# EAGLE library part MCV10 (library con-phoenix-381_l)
Mini-Combicon 3.81mm vertikal 10polig (ohne Gegenstecker)
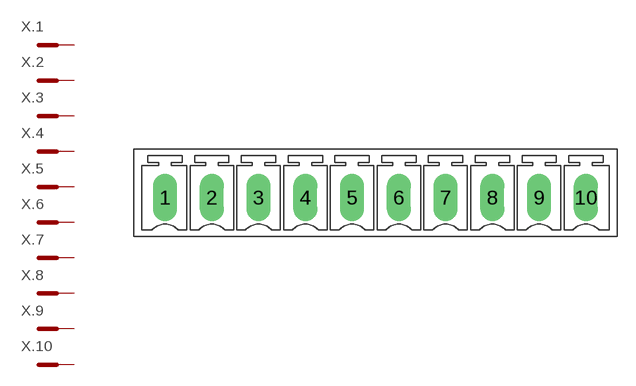
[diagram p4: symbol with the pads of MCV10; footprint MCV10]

Designator prefix X; gates .1=MCST .2=MCST .3=MCST .4=MCST .5=MCST .6=MCST .7=MCST .8=MCST .9=MCST .10=MCST

## MCV10  [MCV10]
1  .1:SK  pas
2  .2:SK  pas
3  .3:SK  pas
4  .4:SK  pas
5  .5:SK  pas
6  .6:SK  pas
7  .7:SK  pas
8  .8:SK  pas
9  .9:SK  pas
10  .10:SK  pas

## Footprint MCV10 (pad centres in mm)
Mini-Combicon 3.81mm vertikal 10-polig (ohne Gegenstecker)
drill 1.3 pad 1.905 long: 1 -17.145,0; 2 -13.335,0; 3 -9.525,0; 4 -5.715,0; 5 -1.905,0; 6 1.905,0; 7 5.715,0; 8 9.525,0; 9 13.335,0; 10 17.145,0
